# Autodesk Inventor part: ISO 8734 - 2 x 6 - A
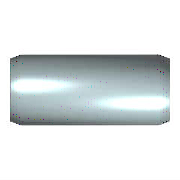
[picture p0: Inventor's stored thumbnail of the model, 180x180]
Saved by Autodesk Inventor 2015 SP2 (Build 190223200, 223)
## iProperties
Created: 2012-02
Part Number: ISO 8734 - 2 x 6 - A
Material: Stahl
Description: Zylinderstift
Document SubType Name: Modeling
Standard: ISO 8734
Designer: rYan
Standards Organization: DIN
Language: de-DE
Size Designation: 2 x 6 - A
Categories: <MemberInstance><Categories><Category DisplayName="Verbindungselemente" InternalName="e4da775c-781d-43d5-af7c-5136215cf5a6" Mnemonic="FSTN"><Category DisplayNam
Density: 7.85 g/cm^3
Mass: 0.146401 g
Surface Area: 0.428007 cm^2
Volume: 0.0186498 cm^3
Appearance: Platte
IsCustomPart: 0
Author: rYan
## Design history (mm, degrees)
sketch "Skizze"
  geometry: C1 r 1 at (0, 0); 1 further point
  constraints: 1 centre point, 1 coincident
  dimensions: "d1" = 2 diameter of C1 (= NND)
extrude "Körper" new body sketch "Skizze" distance "d2" = 6 (= NLG); taper "d3" = 0 deg
body "Solid1"
chamfer "Fase1" distance "d4" = 0.35 (= PHH); stored, may be unused: angle "d5" = 15 deg (= FAWI), second distance "d11" = 0.35 (= PHH)
chamfer "Fase2" distance "d8" = 0.35 (= PHH); stored, may be unused: angle "d9" = 15 deg (= FAWI), second distance "d12" = 0.35 (= PHH)
other parameters: "NND" = 2 [user parameter; used in 1 equation term], "NLG" = 6 [user parameter; used in 1 equation term], "PHH" = 0.35 [user parameter; used in 5 equation terms], "FAWI" = 15 deg [user parameter; used in 2 equation terms], "d13" = 0, "d15" = 0, "d16" = 0, "PHH2" = 0.35 (= PHH) [user parameter], "FAWI2" = 15 deg [user parameter]
